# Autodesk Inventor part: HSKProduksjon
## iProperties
Created: 2009-12
Part Number: HSKProduksjon
Document SubType Name: Modeling
Designer: a31733
Density: 1 g/cm^3
Author: a31733
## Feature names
1. Circular Pattern1
2. Extrusion1
3. Loft1
4. Extrusion2
5. Extrusion4
6. Revolution1
7. Fillet5
8. Fillet6
9. Extrusion5
10. Fillet7
11. Extrusion6
12. Extrusion7
13. Circular Pattern2
14. Hole1
